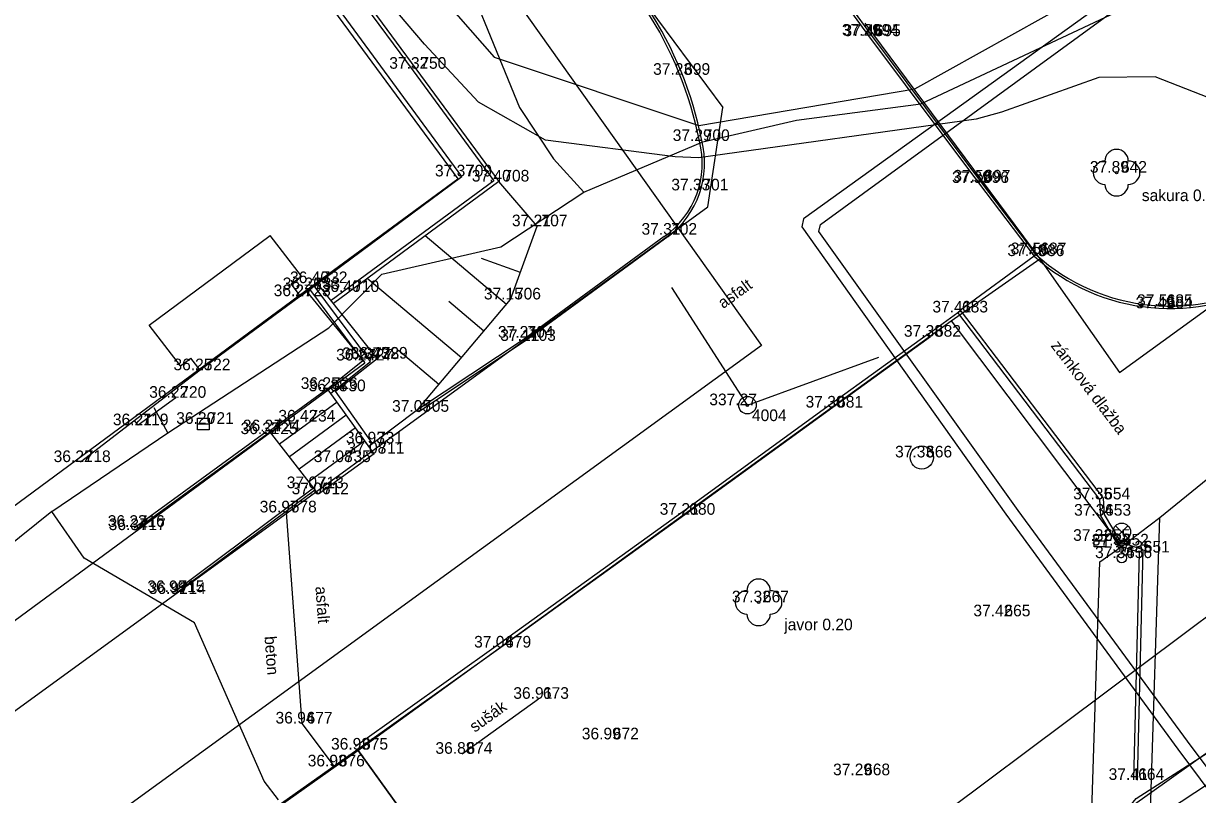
# Model space of a CAD drawing. Extents: x -609709 to -609357, y -1051535 to -1051131.
# Drawn here: x -609620.63 to -609595.44, y -1051316.68 to -1051300.14 of the extents above; entities that cross this region are included whole.
import ezdxf

# ---------------------------------------------------------------- set-up
doc = ezdxf.new("R2010")
doc.units = 0
for name, color, linetype in [('Vrstva 1', 7, 'Continuous'), ('Vrstva 10', 7, 'Continuous'), ('Vrstva 12', 7, 'Continuous'), ('Vrstva 15', 7, 'Continuous'), ('Vrstva 18', 7, 'Continuous'), ('Vrstva 19', 7, 'Continuous'), ('Vrstva 2', 7, 'Continuous'), ('Vrstva 3', 7, 'Continuous'), ('Vrstva 4', 7, 'Continuous'), ('Vrstva 5', 7, 'Continuous'), ('Vrstva 6', 7, 'Continuous'), ('Vrstva 7', 7, 'Continuous'), ('Vrstva 8', 7, 'Continuous'), ('Vrstva 9', 7, 'Continuous')]:
    doc.layers.add(name, color=color, linetype=linetype)

msp = doc.modelspace()

# ---------------------------------------------------------------- linework, layer by layer
at = {"layer": 'Vrstva 1'}
for p, q in [((-609602.5, -1051300.4), (-609602.5, -1051300.4)), ((-609602.46, -1051300.41), (-609602.46, -1051300.41)), ((-609612.21, -1051301.11), (-609612.21, -1051301.11)), ((-609606.55, -1051301.24), (-609606.55, -1051301.24)), ((-609606.13, -1051302.66), (-609606.13, -1051302.66)), ((-609597.18, -1051303.34), (-609597.18, -1051303.34)), ((-609611.23, -1051303.42), (-609611.23, -1051303.42)), ((-609610.43, -1051303.53), (-609610.43, -1051303.53)), ((-609600.14, -1051303.56), (-609600.14, -1051303.56)), ((-609600.11, -1051303.53), (-609600.11, -1051303.53)), ((-609606.16, -1051303.72), (-609606.16, -1051303.72)), ((-609609.61, -1051304.49), (-609609.61, -1051304.49)), ((-609606.83, -1051304.67), (-609606.83, -1051304.67)), ((-609598.95, -1051305.13), (-609598.95, -1051305.13)), ((-609598.91, -1051305.09), (-609598.91, -1051305.09)), ((-609614.49, -1051305.84), (-609614.49, -1051305.84)), ((-609614.33, -1051305.71), (-609614.33, -1051305.71)), ((-609614.69, -1051305.99), (-609614.69, -1051305.99)), ((-609613.65, -1051305.9), (-609613.65, -1051305.9)), ((-609610.18, -1051306.06), (-609610.18, -1051306.06)), ((-609600.59, -1051306.34), (-609600.59, -1051306.34)), ((-609596.2, -1051306.2), (-609596.2, -1051306.2)), ((-609596.2, -1051306.25), (-609596.2, -1051306.25)), ((-609609.91, -1051306.88), (-609609.91, -1051306.88)), ((-609601.17, -1051306.86), (-609601.17, -1051306.86)), ((-609609.86, -1051306.95), (-609609.86, -1051306.95)), ((-609613.35, -1051307.37), (-609613.35, -1051307.37)), ((-609613.22, -1051307.34), (-609613.22, -1051307.34)), ((-609613.04, -1051307.33), (-609613.04, -1051307.33)), ((-609616.84, -1051307.58), (-609616.84, -1051307.58)), ((-609614.11, -1051307.98), (-609614.11, -1051307.98)), ((-609613.94, -1051308.03), (-609613.94, -1051308.03)), ((-609617.36, -1051308.17), (-609617.36, -1051308.17)), ((-609605.1, -1051308.33), (-609605.1, -1051308.33)), ((-609603.27, -1051308.38), (-609603.27, -1051308.38)), ((-609612.15, -1051308.47), (-609612.15, -1051308.47)), ((-609618.17, -1051308.76), (-609618.17, -1051308.76)), ((-609616.77, -1051308.73), (-609616.77, -1051308.73)), ((-609615.35, -1051308.89), (-609615.35, -1051308.89)), ((-609614.59, -1051308.68), (-609614.59, -1051308.68)), ((-609615.4, -1051308.95), (-609615.4, -1051308.95)), ((-609613.14, -1051309.15), (-609613.14, -1051309.15)), ((-609613.11, -1051309.37), (-609613.11, -1051309.37)), ((-609619.41, -1051309.55), (-609619.41, -1051309.55)), ((-609613.83, -1051309.55), (-609613.83, -1051309.55)), ((-609601.36, -1051309.45), (-609601.36, -1051309.45)), ((-609614.41, -1051310.11), (-609614.41, -1051310.11)), ((-609614.3, -1051310.24), (-609614.3, -1051310.24)), ((-609597.54, -1051310.35), (-609597.54, -1051310.35)), ((-609614.99, -1051310.63), (-609614.99, -1051310.63)), ((-609606.44, -1051310.68), (-609606.44, -1051310.68)), ((-609597.52, -1051310.7), (-609597.52, -1051310.7)), ((-609618.25, -1051310.94), (-609618.25, -1051310.94)), ((-609618.23, -1051311.01), (-609618.23, -1051311.01)), ((-609597.54, -1051311.24), (-609597.54, -1051311.24)), ((-609597.14, -1051311.34), (-609597.14, -1051311.34)), ((-609597.07, -1051311.61), (-609597.07, -1051311.61)), ((-609596.69, -1051311.49), (-609596.69, -1051311.49)), ((-609617.4, -1051312.34), (-609617.4, -1051312.34)), ((-609617.37, -1051312.38), (-609617.37, -1051312.38)), ((-609604.86, -1051312.56), (-609604.86, -1051312.56)), ((-609599.68, -1051312.86), (-609599.68, -1051312.86)), ((-609610.39, -1051313.53), (-609610.39, -1051313.53)), ((-609609.58, -1051314.63), (-609609.58, -1051314.63)), ((-609614.65, -1051315.16), (-609614.65, -1051315.16)), ((-609608.08, -1051315.5), (-609608.08, -1051315.5)), ((-609613.46, -1051315.72), (-609613.46, -1051315.72)), ((-609611.22, -1051315.81), (-609611.22, -1051315.81)), ((-609613.96, -1051316.08), (-609613.96, -1051316.08)), ((-609602.69, -1051316.27), (-609602.69, -1051316.27)), ((-609596.81, -1051316.37), (-609596.81, -1051316.37))]:
    msp.add_line(p, q, dxfattribs=at)
at = {"layer": 'Vrstva 10'}
for p, q in [((-609623.67, -1051277.61), (-609605.63, -1051301.94)), ((-609618.08, -1051294.28), (-609611.31, -1051303.47)), ((-609602.58, -1051300.13), (-609598.83, -1051305.19)), ((-609597.12, -1051307.63), (-609588.6, -1051301.43)), ((-609605.95, -1051304.07), (-609605.63, -1051301.94)), ((-609614.57, -1051305.87), (-609611.31, -1051303.47)), ((-609622.29, -1051315.96), (-609605.95, -1051304.07)), ((-609600.73, -1051306.52), (-609598.83, -1051305.19)), ((-609598.83, -1051305.19), (-609597.12, -1051307.63)), ((-609625.94, -1051314.25), (-609614.57, -1051305.87)), ((-609614.57, -1051305.87), (-609613.31, -1051307.42)), ((-609613.46, -1051315.74), (-609600.73, -1051306.52)), ((-609600.73, -1051306.52), (-609597.08, -1051311.37)), ((-609633.67, -1051322.4), (-609613.31, -1051307.42)), ((-609596.25, -1051310.74), (-609594.83, -1051309.58)), ((-609598.65, -1051385.24), (-609596.25, -1051310.74)), ((-609597.08, -1051311.37), (-609596.25, -1051310.74)), ((-609597.54, -1051311.69), (-609597.08, -1051311.37)), ((-609599.55, -1051372.92), (-609597.54, -1051311.69)), ((-609619.44, -1051319.97), (-609613.46, -1051315.74)), ((-609613.46, -1051315.74), (-609609.87, -1051320.71))]:
    msp.add_line(p, q, dxfattribs=at)
at = {"layer": 'Vrstva 12'}
for points in [[(-609617.53, -1051308.92), (-609614.08, -1051306.67), (-609612.94, -1051305.52), (-609610.39, -1051304.93), (-609608.61, -1051303.76), (-609606.06, -1051302.68), (-609604.05, -1051302.21), (-609601.38, -1051301.86), (-609597.07, -1051299.84), (-609592.58, -1051298), (-609588.06, -1051296.22), (-609585.76, -1051295.02), (-609575.12, -1051289.04), (-609565.28, -1051281.43), (-609560.89, -1051277.53), (-609555.76, -1051273.58), (-609560.56, -1051267.09), (-609566.32, -1051260.26), (-609571.84, -1051253.12), (-609574.91, -1051248.7), (-609573.88, -1051248.47), (-609573.078, -1051248.47)], [(-609644.336, -1051251.436), (-609604.801, -1051307.048), (-609620.698, -1051318.606), (-609619.426, -1051320.272)], [(-609598.88, -1051264.1), (-609604.42, -1051268.47), (-609611.68, -1051274.04), (-609616.21, -1051277.75), (-609621.57, -1051284.12), (-609621.25, -1051285.42), (-609619.8, -1051287.45), (-609615.97, -1051291.57), (-609612.96, -1051295.31), (-609611.54, -1051298.14), (-609609.99, -1051301.94), (-609609.26, -1051303.04), (-609608.61, -1051303.76)], [(-609615.546, -1051325.052), (-609614.108, -1051326.974), (-609589.099, -1051308.266), (-609582.815, -1051303.565), (-609514.844, -1051393.856), (-609499.807, -1051382.785), (-609467.693, -1051377.467)], [(-609620.02, -1051310.61), (-609617.53, -1051308.92), (-609617.826, -1051308.389)], [(-609611.146, -1051321.543), (-609608.58, -1051322.92), (-609606.77, -1051324.03), (-609605.35, -1051324.21), (-609598.98, -1051319.18), (-609597.27, -1051317.23), (-609591.09, -1051312.83), (-609587.26, -1051310.28), (-609585.26, -1051309.71), (-609584.965, -1051309.999)], [(-609615.16, -1051316.797), (-609615.47, -1051316.4), (-609616.96, -1051313), (-609619.33, -1051311.61), (-609620.02, -1051310.61), (-609623.46, -1051313.37), (-609631.88, -1051319.51), (-609632.148, -1051319.084)]]:
    msp.add_lwpolyline(points, dxfattribs=at)
at = {"layer": 'Vrstva 15'}
for points in [[(-609590.03, -1051312.18), (-609589.76, -1051311.7), (-609589.53, -1051310.88), (-609589.67, -1051309.74), (-609590.15, -1051307.96), (-609591.04, -1051306.42), (-609592.5, -1051304.31), (-609593.89, -1051302.67), (-609595.04, -1051301.8), (-609596.35, -1051301.28), (-609597.56, -1051301.3), (-609599.65, -1051302.04), (-609600.19, -1051302.19), (-609606.15, -1051303.02), (-609606.65, -1051303), (-609609.43, -1051302.64), (-609610.87, -1051301.83), (-609612.03, -1051300.58), (-609613.35, -1051299.02), (-609614.15, -1051297.61), (-609615.07, -1051296.33), (-609616.17, -1051296.89)], [(-609613.57, -1051297.39), (-609610.53, -1051300.86), (-609606.14, -1051302.33), (-609601.51, -1051301.54), (-609595.96, -1051298.44), (-609593.36, -1051298.96), (-609591.48, -1051303.13), (-609590.4, -1051306.74), (-609588.91, -1051310.41), (-609588.82, -1051311.77), (-609588.19, -1051312.627)], [(-609588.82, -1051311.77), (-609594.6, -1051316.05), (-609596.4, -1051317.24), (-609597.23, -1051322.04), (-609597.58, -1051330.03), (-609597.74, -1051335.22)], [(-609591.07, -1051329.67), (-609593.09, -1051327.12), (-609596.69, -1051324.61), (-609597.37, -1051324.04), (-609598.02, -1051322.6), (-609598.17, -1051321.64), (-609597.8, -1051319.16), (-609597.17, -1051317.27), (-609596.76, -1051316.77), (-609594.67, -1051315.43), (-609593.9, -1051314.91), (-609591.92, -1051313.69), (-609590.24, -1051312.51), (-609590.03, -1051312.18), (-609589.59, -1051312.11), (-609588.92, -1051312.29), (-609588.35, -1051312.29), (-609588.06, -1051312.55)]]:
    msp.add_lwpolyline(points, dxfattribs=at)
at = {"layer": 'Vrstva 18'}
for points in [[(-609605.1, -1051308.33), (-609606.719, -1051305.804)], [(-609605.1, -1051308.33), (-609602.282, -1051307.302)]]:
    msp.add_lwpolyline(points, dxfattribs=at)
for radius in [0.188, 0.025]:
    msp.add_circle((-609605.1, -1051308.33), radius, dxfattribs=at)
at = {"layer": 'Vrstva 19'}
for points in [[(-609589.68, -1051320.38), (-609591.1, -1051321.45), (-609591.26, -1051321.42), (-609595.66, -1051315.54), (-609599.29, -1051310.59), (-609603.57, -1051304.6), (-609603.53, -1051304.45), (-609597.5, -1051300.05), (-609589.44, -1051294.18), (-609579.1, -1051286.55), (-609565.69, -1051276.62), (-609561.84, -1051273.9), (-609561.08, -1051273.38), (-609561.07, -1051273.26), (-609565.31, -1051267.81), (-609569, -1051263.05), (-609568.98, -1051262.9), (-609566.12, -1051260.7)], [(-609561.81, -1051273.58), (-609564.02, -1051275.2), (-609565.73, -1051276.44), (-609579.25, -1051286.33), (-609589.6, -1051294), (-609597.83, -1051299.97), (-609603.9, -1051304.33), (-609603.93, -1051304.5), (-609599.56, -1051310.67), (-609595.87, -1051315.71), (-609591.35, -1051321.78), (-609591.2, -1051321.8), (-609589.56, -1051320.54)]]:
    msp.add_lwpolyline(points, dxfattribs=at)
at = {"layer": 'Vrstva 4'}
for p, q in [((-609614.265, -1051298.457), (-609612.274, -1051301.157)), ((-609606.886, -1051304.711), (-609609.889, -1051306.909)), ((-609609.889, -1051306.909), (-609612.178, -1051308.428)), ((-609613.904, -1051308.266), (-609615.135, -1051309.166)), ((-609613.706, -1051308.542), (-609614.926, -1051309.435)), ((-609615.429, -1051308.91), (-609618.259, -1051310.97)), ((-609613.507, -1051308.818), (-609614.718, -1051309.703)), ((-609613.309, -1051309.094), (-609614.509, -1051309.972)), ((-609614.38, -1051310.15), (-609617.37, -1051312.38))]:
    msp.add_line(p, q, dxfattribs=at)
for points in [[(-609610.218, -1051289.752), (-609607.65, -1051293.43), (-609605.22, -1051296.67), (-609602.5, -1051300.4), (-609600.14, -1051303.56), (-609598.95, -1051305.13)], [(-609610.177, -1051289.724), (-609607.609, -1051293.401), (-609605.18, -1051296.64), (-609602.46, -1051300.37), (-609600.1, -1051303.53), (-609598.913, -1051305.096)], [(-609620.48, -1051295.31), (-609618.34, -1051293.66), (-609617.88, -1051293.34), (-609614.2, -1051298.41), (-609612.21, -1051301.11), (-609610.43, -1051303.53), (-609613.983, -1051306.145)], [(-609612.274, -1051301.157), (-609610.542, -1051303.513), (-609614.033, -1051306.083)], [(-609606.8, -1051304.71), (-609609.86, -1051306.95)], [(-609598.95, -1051305.13), (-609600.526, -1051306.292)], [(-609614.11, -1051307.98), (-609613.35, -1051307.37), (-609614.49, -1051305.84)], [(-609614.035, -1051308.074), (-609613.185, -1051307.391), (-609614.394, -1051305.768)], [(-609613.14, -1051309.15), (-609613.94, -1051308.03), (-609613.04, -1051307.33), (-609614.324, -1051305.718)], [(-609601.217, -1051306.795), (-609600.59, -1051306.34), (-609600.526, -1051306.292)], [(-609596.81, -1051316.37), (-609596.69, -1051311.49), (-609597.14, -1051311.34), (-609597.52, -1051310.7), (-609597.54, -1051310.35), (-609600.59, -1051306.34)], [(-609596.73, -1051316.372), (-609596.609, -1051311.433), (-609597.086, -1051311.274), (-609597.441, -1051310.676), (-609597.462, -1051310.321), (-609600.526, -1051306.292)], [(-609601.217, -1051306.795), (-609603.317, -1051308.315), (-609606.487, -1051310.615), (-609610.437, -1051313.465), (-609613.506, -1051315.655)], [(-609601.17, -1051306.86), (-609603.27, -1051308.38), (-609606.44, -1051310.68), (-609610.39, -1051313.53), (-609613.46, -1051315.72)], [(-609601.17, -1051306.86), (-609601.217, -1051306.795)], [(-609609.86, -1051306.95), (-609612.15, -1051308.47)], [(-609614.11, -1051307.98), (-609615.35, -1051308.89)], [(-609613.11, -1051309.37), (-609614.11, -1051307.98)], [(-609612.178, -1051308.428), (-609613.223, -1051309.212)], [(-609612.15, -1051308.47), (-609612.178, -1051308.428)], [(-609615.4, -1051308.95), (-609615.429, -1051308.91)], [(-609614.3, -1051310.24), (-609615.35, -1051308.89)], [(-609615.4, -1051308.95), (-609618.23, -1051311.01)], [(-609613.11, -1051309.37), (-609614.3, -1051310.24)], [(-609614.41, -1051310.11), (-609617.4, -1051312.34)], [(-609614.41, -1051310.11), (-609614.38, -1051310.15)], [(-609613.96, -1051316.08), (-609614.65, -1051315.16), (-609614.99, -1051310.63)]]:
    msp.add_lwpolyline(points, dxfattribs=at)
for centre, radius, start, end in [((-609614.056, -1051304.232), 8.081, 11.2198, 33.01), ((-609614.056, -1051304.232), 8.131, 11.2294, 33.013), ((-609607.994, -1051303.138), 1.924, 305.171, 14.3716), ((-609607.994, -1051303.138), 1.974, 307.2261, 14.3315), ((-609596.044, -1051301.93), 4.323, 227.7545, 301.5297), ((-609596.044, -1051301.93), 4.273, 227.8165, 301.5028)]:
    msp.add_arc(centre, radius, start, end, dxfattribs=at)
at = {"layer": 'Vrstva 5'}
for p, q in [((-609616.895, -1051308.73), (-609616.645, -1051308.73)), ((-609597.203, -1051311.18), (-609596.938, -1051310.915)), ((-609597.203, -1051310.915), (-609596.938, -1051311.18)), ((-609597.665, -1051311.24), (-609597.415, -1051311.24)), ((-609597.07, -1051311.235), (-609597.07, -1051311.51))]:
    msp.add_line(p, q, dxfattribs=at)
for points in [[(-609616.895, -1051308.605), (-609616.645, -1051308.605), (-609616.645, -1051308.855), (-609616.895, -1051308.855)], [(-609597.665, -1051311.115), (-609597.415, -1051311.115), (-609597.415, -1051311.365), (-609597.665, -1051311.365)]]:
    msp.add_lwpolyline(points, close=True, dxfattribs=at)
msp.add_lwpolyline([(-609611.22, -1051315.81), (-609609.58, -1051314.63)], dxfattribs=at)
for centre, radius in [((-609601.36, -1051309.45), 0.25), ((-609597.07, -1051311.048), 0.188), ((-609597.07, -1051311.61), 0.1)]:
    msp.add_circle(centre, radius, dxfattribs=at)
at = {"layer": 'Vrstva 6'}
msp.add_lwpolyline([(-609612.178, -1051308.428), (-609610.18, -1051306.06), (-609609.61, -1051304.49), (-609610.43, -1051303.53)], dxfattribs=at)
at = {"layer": 'Vrstva 7'}
for centre in [(-609597.18, -1051303.34), (-609604.86, -1051312.56)]:
    msp.add_circle(centre, 0.025, dxfattribs=at)
for centre, start, end in [((-609597.18, -1051303.09), 0, 180), ((-609597.43, -1051303.34), 90, 270), ((-609596.93, -1051303.34), 270, 90), ((-609597.18, -1051303.59), 180, 0), ((-609604.86, -1051312.31), 0, 180), ((-609605.11, -1051312.56), 90, 270), ((-609604.61, -1051312.56), 270, 90), ((-609604.86, -1051312.81), 180, 0)]:
    msp.add_arc(centre, 0.25, start, end, dxfattribs=at)
at = {"layer": 'Vrstva 8'}
for p, q in [((-609610.269, -1051306.165), (-609612.012, -1051304.694)), ((-609609.971, -1051305.484), (-609610.805, -1051305.181)), ((-609611.236, -1051307.312), (-609613.254, -1051305.609)), ((-609610.752, -1051306.738), (-609611.505, -1051306.104)), ((-609611.719, -1051307.885), (-609612.582, -1051307.157))]:
    msp.add_line(p, q, dxfattribs=at)
at = {"layer": 'Vrstva 9'}
for points in [[(-609614.69, -1051305.99), (-609611.23, -1051303.42), (-609618, -1051294.19), (-609620.16, -1051295.78)], [(-609617.932, -1051306.615), (-609615.338, -1051304.685)], [(-609614.669, -1051305.558), (-609615.338, -1051304.685)], [(-609614.891, -1051305.728), (-609614.669, -1051305.558)], [(-609614.69, -1051305.99), (-609614.891, -1051305.728)], [(-609614.69, -1051305.99), (-609616.84, -1051307.58)], [(-609617.263, -1051307.488), (-609617.932, -1051306.615)], [(-609617.263, -1051307.488), (-609617.041, -1051307.318)], [(-609616.84, -1051307.58), (-609617.041, -1051307.318)], [(-609616.84, -1051307.58), (-609619.41, -1051309.55)], [(-609617.36, -1051308.17), (-609617.452, -1051308.049)], [(-609617.36, -1051308.17), (-609618.17, -1051308.76), (-609618.247, -1051308.659)], [(-609609.89, -1051320.68), (-609613.46, -1051315.72), (-609617.194, -1051318.361)]]:
    msp.add_lwpolyline(points, dxfattribs=at)

# ---------------------------------------------------------------- texts
at = {"layer": 'Vrstva 18'}
msp.add_text(' 4004', height=0.25, dxfattribs=at).set_placement((-609605.096, -1051308.67))
at = {"layer": 'Vrstva 2'}
for s, p in [(' 694', (-609602.5, -1051300.4)), (' 695', (-609602.46, -1051300.41)), (' 750', (-609612.21, -1051301.11)), (' 699', (-609606.55, -1051301.24)), (' 700', (-609606.13, -1051302.66)), (' 642', (-609597.18, -1051303.34)), (' 709', (-609611.23, -1051303.42)), (' 708', (-609610.43, -1051303.53)), (' 696', (-609600.14, -1051303.56)), (' 697', (-609600.11, -1051303.53)), (' 701', (-609606.16, -1051303.72)), (' 707', (-609609.61, -1051304.49)), (' 702', (-609606.83, -1051304.67)), (' 686', (-609598.95, -1051305.13)), (' 687', (-609598.91, -1051305.09)), (' 733', (-609614.49, -1051305.84)), (' 732', (-609614.33, -1051305.71)), (' 723', (-609614.69, -1051305.99)), (' 710', (-609613.65, -1051305.9)), (' 706', (-609610.18, -1051306.06)), (' 683', (-609600.59, -1051306.34)), (' 685', (-609596.2, -1051306.2)), (' 684', (-609596.2, -1051306.25)), (' 704', (-609609.91, -1051306.88)), (' 682', (-609601.17, -1051306.86)), (' 703', (-609609.86, -1051306.95)), (' 727', (-609613.35, -1051307.37)), (' 728', (-609613.22, -1051307.34)), (' 729', (-609613.04, -1051307.33)), (' 722', (-609616.84, -1051307.58)), (' 726', (-609614.11, -1051307.98)), (' 730', (-609613.94, -1051308.03)), (' 720', (-609617.36, -1051308.17)), (' 681', (-609603.27, -1051308.38)), (' 705', (-609612.15, -1051308.47)), (' 719', (-609618.17, -1051308.76)), (' 721', (-609616.77, -1051308.73)), (' 724', (-609615.35, -1051308.89)), (' 734', (-609614.59, -1051308.68)), (' 725', (-609615.4, -1051308.95)), (' 731', (-609613.14, -1051309.15)), (' 711', (-609613.11, -1051309.37)), (' 718', (-609619.41, -1051309.55)), (' 735', (-609613.83, -1051309.55)), (' 666', (-609601.36, -1051309.45)), (' 713', (-609614.41, -1051310.11)), (' 712', (-609614.3, -1051310.24)), (' 654', (-609597.54, -1051310.35)), (' 678', (-609614.99, -1051310.63)), (' 680', (-609606.44, -1051310.68)), (' 653', (-609597.52, -1051310.7)), (' 716', (-609618.25, -1051310.94)), (' 717', (-609618.23, -1051311.01)), (' 655', (-609597.54, -1051311.24)), (' 652', (-609597.14, -1051311.34)), (' 656', (-609597.07, -1051311.61)), (' 651', (-609596.69, -1051311.49)), (' 715', (-609617.4, -1051312.34)), (' 714', (-609617.37, -1051312.38)), (' 667', (-609604.86, -1051312.56)), (' 665', (-609599.68, -1051312.86)), (' 679', (-609610.39, -1051313.53)), (' 673', (-609609.58, -1051314.63)), (' 677', (-609614.65, -1051315.16)), (' 672', (-609608.08, -1051315.5)), (' 675', (-609613.46, -1051315.72)), (' 674', (-609611.22, -1051315.81)), (' 676', (-609613.96, -1051316.08)), (' 668', (-609602.69, -1051316.27)), (' 664', (-609596.81, -1051316.37))]:
    msp.add_text(s, height=0.25, dxfattribs=at).set_placement(p)
at = {"layer": 'Vrstva 3'}
for s, p in [('37.29', (-609603.073, -1051300.4)), ('37.46', (-609603.039, -1051300.41)), ('37.32', (-609612.783, -1051301.11)), ('37.23', (-609607.123, -1051301.24)), ('37.29', (-609606.703, -1051302.66)), ('37.89', (-609597.753, -1051303.34)), ('37.37', (-609611.803, -1051303.42)), ('37.40', (-609611.013, -1051303.53)), ('37.39', (-609600.713, -1051303.56)), ('37.53', (-609600.683, -1051303.53)), ('37.33', (-609606.733, -1051303.72)), ('37.21', (-609610.152, -1051304.49)), ('37.31', (-609607.372, -1051304.67)), ('37.49', (-609599.523, -1051305.13)), ('37.51', (-609599.452, -1051305.09)), ('36.26', (-609615.069, -1051305.84)), ('36.40', (-609614.913, -1051305.71)), ('36.27', (-609615.263, -1051305.99)), ('36.40', (-609614.233, -1051305.9)), ('37.15', (-609610.753, -1051306.06)), ('37.41', (-609601.132, -1051306.34)), ('37.49', (-609596.773, -1051306.25)), ('37.51', (-609596.742, -1051306.2)), ('37.21', (-609610.452, -1051306.88)), ('37.38', (-609601.743, -1051306.86)), ('37.11', (-609610.402, -1051306.95)), ('36.24', (-609613.923, -1051307.37)), ('36.37', (-609613.793, -1051307.34)), ('36.43', (-609613.613, -1051307.33)), ('36.25', (-609617.413, -1051307.58)), ('36.25', (-609614.683, -1051307.98)), ('36.38', (-609614.513, -1051308.03)), ('36.22', (-609617.933, -1051308.17)), ('337.27', (-609605.918, -1051308.33)), ('37.30', (-609603.853, -1051308.38)), ('37.05', (-609612.723, -1051308.47)), ('36.21', (-609618.712, -1051308.76)), ('36.20', (-609617.353, -1051308.73)), ('36.24', (-609615.923, -1051308.89)), ('36.42', (-609615.163, -1051308.68)), ('36.32', (-609615.973, -1051308.95)), ('36.93', (-609613.713, -1051309.15)), ('37.08', (-609613.683, -1051309.37)), ('36.22', (-609619.983, -1051309.55)), ('37.08', (-609614.403, -1051309.55)), ('37.33', (-609601.933, -1051309.45)), ('37.07', (-609614.983, -1051310.11)), ('37.06', (-609614.879, -1051310.24)), ('37.35', (-609598.113, -1051310.35)), ('36.97', (-609615.563, -1051310.63)), ('37.21', (-609606.982, -1051310.68)), ('37.34', (-609598.093, -1051310.7)), ('36.23', (-609618.823, -1051310.94)), ('36.34', (-609618.803, -1051311.01)), ('37.32', (-609598.113, -1051311.24)), ('37.33', (-609597.713, -1051311.34)), ('37.34', (-609597.643, -1051311.61)), ('37.35', (-609597.263, -1051311.49)), ('36.99', (-609617.973, -1051312.34)), ('36.92', (-609617.943, -1051312.38)), ('37.32', (-609605.433, -1051312.56)), ('37.42', (-609600.253, -1051312.86)), ('37.04', (-609610.963, -1051313.53)), ('36.91', (-609610.122, -1051314.63)), ('36.94', (-609615.223, -1051315.16)), ('36.99', (-609608.653, -1051315.5)), ('36.93', (-609614.033, -1051315.72)), ('36.88', (-609611.793, -1051315.81)), ('36.93', (-609614.533, -1051316.08)), ('37.29', (-609603.263, -1051316.27)), ('37.41', (-609597.352, -1051316.37))]:
    msp.add_text(s, height=0.25, dxfattribs=at).set_placement(p)
at = {"layer": 'Vrstva 4'}
for s, rotation, p in [('asfalt', 35.8112, (-609605.62, -1051306.267)), ('zámková dlažba', 307.2566, (-609598.603, -1051307.055)), ('asfalt', 274.2923, (-609614.369, -1051312.224)), ('beton', 274.2923, (-609615.46, -1051313.293))]:
    msp.add_text(s, height=0.25, rotation=rotation, dxfattribs=at).set_placement(p)
at = {"layer": 'Vrstva 5'}
msp.add_text('sušák', height=0.25, rotation=35.7355, dxfattribs=at).set_placement((-609610.949, -1051315.36))
at = {"layer": 'Vrstva 7'}
for s, p in [('sakura 0.50', (-609596.64, -1051303.95)), ('javor 0.20', (-609604.31, -1051313.16))]:
    msp.add_text(s, height=0.25, dxfattribs=at).set_placement(p)

doc.saveas('drawing.dxf')
